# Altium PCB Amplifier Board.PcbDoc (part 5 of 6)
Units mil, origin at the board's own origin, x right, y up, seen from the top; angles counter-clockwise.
Board outline 6000 x 2640 mil, 6 copper layers (Top Layer, GND, VCC, BASES, GND (Plane3), Bottom Layer), stack 63.9 mil thick; 884 components, 484 nets, 2029 pads, 464 vias.
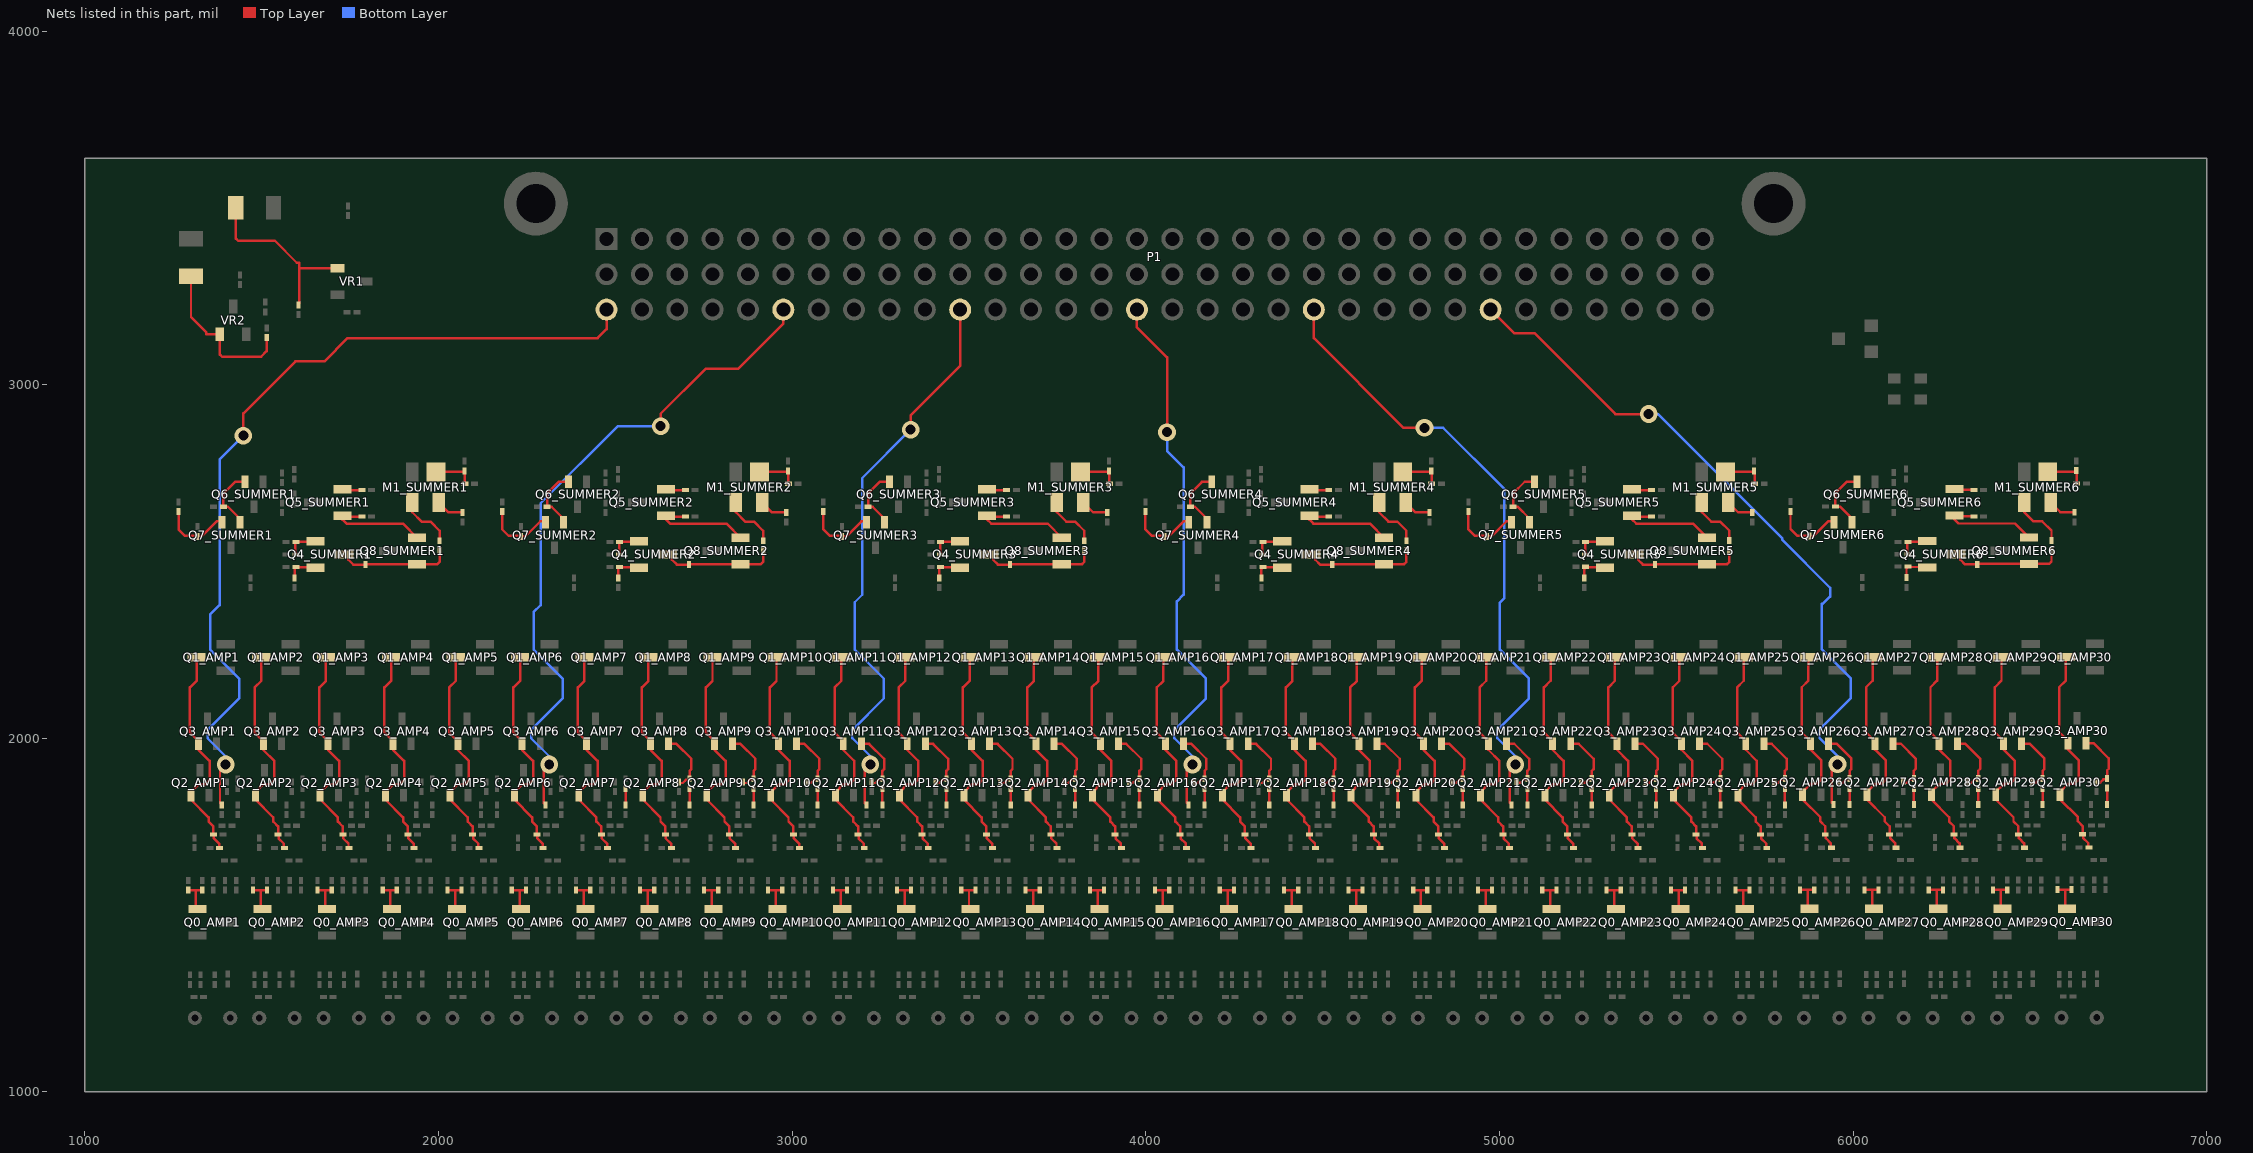
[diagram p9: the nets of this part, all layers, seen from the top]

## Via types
v1: diameter 50, hole 28, Top Layer to Bottom Layer, 433 vias
v2: diameter 50, hole 28, Top Layer to Bottom Layer, tented top, 31 vias

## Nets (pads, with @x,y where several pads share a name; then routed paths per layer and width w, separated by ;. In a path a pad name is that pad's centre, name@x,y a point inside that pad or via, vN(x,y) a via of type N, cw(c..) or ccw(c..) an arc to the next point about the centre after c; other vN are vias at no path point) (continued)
NetC6_AMP7_2: C6_AMP7.2 R7_AMP7.1 | length 42.4
  Top Layer w7: R7_AMP7.1@2529,1812.78 C6_AMP7.2@2529,1855.22
NetC6_AMP8_1: C6_AMP8.1 Q3_AMP8.2 R8_AMP8.1 | length 177.2
  Top Layer w7: Q3_AMP8.2@2650.59,1984.57 2672.68,1984.57 2715,1942.24 2715,1912.94 2710,1907.94 C6_AMP8.1@2710,1885.78 2710,1882.78 2699.59,1882.78 2690.59,1873.78 R8_AMP8.1@2680,1873.78
NetC6_AMP8_2: C6_AMP8.2 R7_AMP8.1 | length 42.4
  Top Layer w7: R7_AMP8.1@2710,1812.78 C6_AMP8.2@2710,1855.22
NetC6_AMP9_1: C6_AMP9.1 Q3_AMP9.2 R8_AMP9.1 | length 177.2
  Top Layer w7: Q3_AMP9.2@2831.59,1984.57 2853.68,1984.57 2896,1942.24 2896,1912.94 2891,1907.94 C6_AMP9.1@2891,1885.78 2891,1882.78 2880.59,1882.78 2871.59,1873.78 R8_AMP9.1@2861,1873.78
NetC6_AMP9_2: C6_AMP9.2 R7_AMP9.1 | length 42.4
  Top Layer w7: R7_AMP9.1@2891,1812.78 C6_AMP9.2@2891,1855.22
NetC6_AMP10_1: C6_AMP10.1 Q3_AMP10.2 R8_AMP10.1 | length 177.2
  Top Layer w7: Q3_AMP10.2@3012.59,1984.57 3034.68,1984.57 3077,1942.24 3077,1912.94 3072,1907.94 C6_AMP10.1@3072,1885.78 3072,1882.78 3061.59,1882.78 3052.59,1873.78 R8_AMP10.1@3042,1873.78
NetC6_AMP10_2: C6_AMP10.2 R7_AMP10.1 | length 42.4
  Top Layer w7: R7_AMP10.1@3072,1812.78 C6_AMP10.2@3072,1855.22
NetC6_AMP11_1: C6_AMP11.1 Q3_AMP11.2 R8_AMP11.1 | length 177.2
  Top Layer w7: Q3_AMP11.2@3195.59,1984.57 3217.68,1984.57 3260,1942.24 3260,1912.94 3255,1907.94 C6_AMP11.1@3255,1885.78 3255,1882.78 3244.59,1882.78 3235.59,1873.78 R8_AMP11.1@3225,1873.78
NetC6_AMP11_2: C6_AMP11.2 R7_AMP11.1 | length 42.4
  Top Layer w7: R7_AMP11.1@3255,1812.78 C6_AMP11.2@3255,1855.22
NetC6_AMP12_1: C6_AMP12.1 Q3_AMP12.2 R8_AMP12.1 | length 177.2
  Top Layer w7: Q3_AMP12.2@3376.59,1984.57 3398.68,1984.57 3441,1942.24 3441,1912.94 3436,1907.94 C6_AMP12.1@3436,1885.78 3436,1882.78 3425.59,1882.78 3416.59,1873.78 R8_AMP12.1@3406,1873.78
NetC6_AMP12_2: C6_AMP12.2 R7_AMP12.1 | length 42.4
  Top Layer w7: R7_AMP12.1@3436,1812.78 C6_AMP12.2@3436,1855.22
NetC6_AMP13_1: C6_AMP13.1 Q3_AMP13.2 R8_AMP13.1 | length 177.2
  Top Layer w7: Q3_AMP13.2@3558.59,1984.57 3580.68,1984.57 3623,1942.24 3623,1912.94 3618,1907.94 C6_AMP13.1@3618,1885.78 3618,1882.78 3607.59,1882.78 3598.59,1873.78 R8_AMP13.1@3588,1873.78
NetC6_AMP13_2: C6_AMP13.2 R7_AMP13.1 | length 42.4
  Top Layer w7: R7_AMP13.1@3618,1812.78 C6_AMP13.2@3618,1855.22
NetC6_AMP14_1: C6_AMP14.1 Q3_AMP14.2 R8_AMP14.1 | length 177.2
  Top Layer w7: Q3_AMP14.2@3740.59,1984.57 3762.68,1984.57 3805,1942.24 3805,1912.94 3800,1907.94 C6_AMP14.1@3800,1885.78 3800,1882.78 3789.59,1882.78 3780.59,1873.78 R8_AMP14.1@3770,1873.78
NetC6_AMP14_2: C6_AMP14.2 R7_AMP14.1 | length 42.4
  Top Layer w7: R7_AMP14.1@3800,1812.78 C6_AMP14.2@3800,1855.22
NetC6_AMP15_1: C6_AMP15.1 Q3_AMP15.2 R8_AMP15.1 | length 177.2
  Top Layer w7: Q3_AMP15.2@3922.59,1984.57 3944.68,1984.57 3987,1942.24 3987,1912.94 3982,1907.94 C6_AMP15.1@3982,1885.78 3982,1882.78 3971.59,1882.78 3962.59,1873.78 R8_AMP15.1@3952,1873.78
NetC6_AMP15_2: C6_AMP15.2 R7_AMP15.1 | length 42.4
  Top Layer w7: R7_AMP15.1@3982,1812.78 C6_AMP15.2@3982,1855.22
NetC6_AMP16_1: C6_AMP16.1 Q3_AMP16.2 R8_AMP16.1 | length 177.2
  Top Layer w7: Q3_AMP16.2@4106.59,1984.57 4128.68,1984.57 4171,1942.24 4171,1912.94 4166,1907.94 C6_AMP16.1@4166,1885.78 4166,1882.78 4155.59,1882.78 4146.59,1873.78 R8_AMP16.1@4136,1873.78
NetC6_AMP16_2: C6_AMP16.2 R7_AMP16.1 | length 42.4
  Top Layer w7: R7_AMP16.1@4166,1812.78 C6_AMP16.2@4166,1855.22
NetC6_AMP17_1: C6_AMP17.1 Q3_AMP17.2 R8_AMP17.1 | length 177.2
  Top Layer w7: Q3_AMP17.2@4289.59,1984.57 4311.68,1984.57 4354,1942.24 4354,1912.94 4349,1907.94 C6_AMP17.1@4349,1885.78 4349,1882.78 4338.59,1882.78 4329.59,1873.78 R8_AMP17.1@4319,1873.78
NetC6_AMP17_2: C6_AMP17.2 R7_AMP17.1 | length 42.4
  Top Layer w7: R7_AMP17.1@4349,1812.78 C6_AMP17.2@4349,1855.22
NetC6_AMP18_1: C6_AMP18.1 Q3_AMP18.2 R8_AMP18.1 | length 177.2
  Top Layer w7: Q3_AMP18.2@4471.59,1984.57 4493.68,1984.57 4536,1942.24 4536,1912.94 4531,1907.94 C6_AMP18.1@4531,1885.78 4531,1882.78 4520.59,1882.78 4511.59,1873.78 R8_AMP18.1@4501,1873.78
NetC6_AMP18_2: C6_AMP18.2 R7_AMP18.1 | length 42.4
  Top Layer w7: R7_AMP18.1@4531,1812.78 C6_AMP18.2@4531,1855.22
NetC6_AMP19_1: C6_AMP19.1 Q3_AMP19.2 R8_AMP19.1 | length 177.2
  Top Layer w7: Q3_AMP19.2@4653.59,1984.57 4675.68,1984.57 4718,1942.24 4718,1912.94 4713,1907.94 C6_AMP19.1@4713,1885.78 4713,1882.78 4702.59,1882.78 4693.59,1873.78 R8_AMP19.1@4683,1873.78
NetC6_AMP19_2: C6_AMP19.2 R7_AMP19.1 | length 42.4
  Top Layer w7: R7_AMP19.1@4713,1812.78 C6_AMP19.2@4713,1855.22
NetC6_AMP20_1: C6_AMP20.1 Q3_AMP20.2 R8_AMP20.1 | length 177.2
  Top Layer w7: Q3_AMP20.2@4836.59,1984.57 4858.68,1984.57 4901,1942.24 4901,1912.94 4896,1907.94 C6_AMP20.1@4896,1885.78 4896,1882.78 4885.59,1882.78 4876.59,1873.78 R8_AMP20.1@4866,1873.78
NetC6_AMP20_2: C6_AMP20.2 R7_AMP20.1 | length 42.4
  Top Layer w7: R7_AMP20.1@4896,1812.78 C6_AMP20.2@4896,1855.22
NetC6_AMP21_1: C6_AMP21.1 Q3_AMP21.2 R8_AMP21.1 | length 177.2
  Top Layer w7: Q3_AMP21.2@5019.59,1984.67 5041.68,1984.67 5084,1942.35 5084,1913.04 5079,1908.04 C6_AMP21.1@5079,1885.88 5079,1882.88 5068.59,1882.88 5059.59,1873.88 R8_AMP21.1@5049,1873.88
NetC6_AMP21_2: C6_AMP21.2 R7_AMP21.1 | length 42.4
  Top Layer w7: R7_AMP21.1@5079,1812.88 C6_AMP21.2@5079,1855.32
NetC6_AMP22_1: C6_AMP22.1 Q3_AMP22.2 R8_AMP22.1 | length 177.2
  Top Layer w7: Q3_AMP22.2@5201.59,1984.67 5223.68,1984.67 5266,1942.35 5266,1913.04 5261,1908.04 C6_AMP22.1@5261,1885.88 5261,1882.88 5250.59,1882.88 5241.59,1873.88 R8_AMP22.1@5231,1873.88
NetC6_AMP22_2: C6_AMP22.2 R7_AMP22.1 | length 42.4
  Top Layer w7: R7_AMP22.1@5261,1812.88 C6_AMP22.2@5261,1855.32
NetC6_AMP23_1: C6_AMP23.1 Q3_AMP23.2 R8_AMP23.1 | length 177.2
  Top Layer w7: Q3_AMP23.2@5383.59,1984.67 5405.68,1984.67 5448,1942.35 5448,1913.04 5443,1908.04 C6_AMP23.1@5443,1885.88 5443,1882.88 5432.59,1882.88 5423.59,1873.88 R8_AMP23.1@5413,1873.88
NetC6_AMP23_2: C6_AMP23.2 R7_AMP23.1 | length 42.4
  Top Layer w7: R7_AMP23.1@5443,1812.88 C6_AMP23.2@5443,1855.32
NetC6_AMP24_1: C6_AMP24.1 Q3_AMP24.2 R8_AMP24.1 | length 177.2
  Top Layer w7: Q3_AMP24.2@5565.59,1984.67 5587.68,1984.67 5630,1942.35 5630,1913.04 5625,1908.04 C6_AMP24.1@5625,1885.88 5625,1882.88 5614.59,1882.88 5605.59,1873.88 R8_AMP24.1@5595,1873.88
NetC6_AMP24_2: C6_AMP24.2 R7_AMP24.1 | length 42.4
  Top Layer w7: R7_AMP24.1@5625,1812.88 C6_AMP24.2@5625,1855.32
NetC6_AMP25_1: C6_AMP25.1 Q3_AMP25.2 R8_AMP25.1 | length 177.2
  Top Layer w7: Q3_AMP25.2@5747.59,1984.67 5769.68,1984.67 5812,1942.35 5812,1913.04 5807,1908.04 C6_AMP25.1@5807,1885.88 5807,1882.88 5796.59,1882.88 5787.59,1873.88 R8_AMP25.1@5777,1873.88
NetC6_AMP25_2: C6_AMP25.2 R7_AMP25.1 | length 42.4
  Top Layer w7: R7_AMP25.1@5807,1812.88 C6_AMP25.2@5807,1855.32
NetC6_AMP26_1: C6_AMP26.1 Q3_AMP26.2 R8_AMP26.1 | length 177.2
  Top Layer w7: Q3_AMP26.2@5930.59,1985.14 5952.68,1985.14 5995,1942.81 5995,1913.51 5990,1908.51 C6_AMP26.1@5990,1886.35 5990,1883.35 5979.59,1883.35 5970.59,1874.35 R8_AMP26.1@5960,1874.35
NetC6_AMP26_2: C6_AMP26.2 R7_AMP26.1 | length 42.4
  Top Layer w7: R7_AMP26.1@5990,1813.35 C6_AMP26.2@5990,1855.79
NetC6_AMP27_1: C6_AMP27.1 Q3_AMP27.2 R8_AMP27.1 | length 177.2
  Top Layer w7: Q3_AMP27.2@6112.59,1985.14 6134.68,1985.14 6177,1942.81 6177,1913.51 6172,1908.51 C6_AMP27.1@6172,1886.35 6172,1883.35 6161.59,1883.35 6152.59,1874.35 R8_AMP27.1@6142,1874.35
NetC6_AMP27_2: C6_AMP27.2 R7_AMP27.1 | length 42.4
  Top Layer w7: R7_AMP27.1@6172,1813.35 C6_AMP27.2@6172,1855.79
NetC6_AMP28_1: C6_AMP28.1 Q3_AMP28.2 R8_AMP28.1 | length 177.2
  Top Layer w7: Q3_AMP28.2@6294.59,1985.14 6316.68,1985.14 6359,1942.81 6359,1913.51 6354,1908.51 C6_AMP28.1@6354,1886.35 6354,1883.35 6343.59,1883.35 6334.59,1874.35 R8_AMP28.1@6324,1874.35
NetC6_AMP28_2: C6_AMP28.2 R7_AMP28.1 | length 42.4
  Top Layer w7: R7_AMP28.1@6354,1813.35 C6_AMP28.2@6354,1855.79
NetC6_AMP29_1: C6_AMP29.1 Q3_AMP29.2 R8_AMP29.1 | length 177.2
  Top Layer w7: Q3_AMP29.2@6476.59,1985.14 6498.68,1985.14 6541,1942.81 6541,1913.51 6536,1908.51 C6_AMP29.1@6536,1886.35 6536,1883.35 6525.59,1883.35 6516.59,1874.35 R8_AMP29.1@6506,1874.35
NetC6_AMP29_2: C6_AMP29.2 R7_AMP29.1 | length 42.4
  Top Layer w7: R7_AMP29.1@6536,1813.35 C6_AMP29.2@6536,1855.79
NetC6_AMP30_1: C6_AMP30.1 Q3_AMP30.2 R8_AMP30.1 | length 177.2
  Top Layer w7: Q3_AMP30.2@6658.59,1985.57 6680.68,1985.57 6723,1943.24 6723,1913.94 6718,1908.94 C6_AMP30.1@6718,1886.78 6718,1883.78 6707.59,1883.78 6698.59,1874.78 R8_AMP30.1@6688,1874.78
NetC6_AMP30_2: C6_AMP30.2 R7_AMP30.1 | length 42.4
  Top Layer w7: R7_AMP30.1@6718,1813.78 C6_AMP30.2@6718,1856.22
NetC7_SUMMER1_2: C7_SUMMER1.2 Q4_SUMMER1.2 R12_SUMMER1.2 | length 76.4
  Top Layer w7: C7_SUMMER1.2@1593,2453.78 1593,2479.22 1597.78,2484 Q4_SUMMER1.2@1642,2484
NetC7_SUMMER2_2: C7_SUMMER2.2 Q4_SUMMER2.2 R12_SUMMER2.2 | length 76.4
  Top Layer w7: C7_SUMMER2.2@2508,2453.78 2508,2479.22 2512.78,2484 Q4_SUMMER2.2@2557,2484
NetC7_SUMMER3_2: C7_SUMMER3.2 Q4_SUMMER3.2 R12_SUMMER3.2 | length 76.4
  Top Layer w7: C7_SUMMER3.2@3416,2453.78 3416,2479.22 3420.78,2484 Q4_SUMMER3.2@3465,2484
NetC7_SUMMER4_2: C7_SUMMER4.2 Q4_SUMMER4.2 R12_SUMMER4.2 | length 76.4
  Top Layer w7: C7_SUMMER4.2@4327,2453.78 4327,2479.22 4331.78,2484 Q4_SUMMER4.2@4376,2484
NetC7_SUMMER5_2: C7_SUMMER5.2 Q4_SUMMER5.2 R12_SUMMER5.2 | length 76.4
  Top Layer w7: C7_SUMMER5.2@5240,2453.88 5240,2479.32 5244.78,2484.1 Q4_SUMMER5.2@5289,2484.1
NetC7_SUMMER6_2: C7_SUMMER6.2 Q4_SUMMER6.2 R12_SUMMER6.2 | length 76.4
  Top Layer w7: C7_SUMMER6.2@6151,2454.35 6151,2479.79 6155.78,2484.57 Q4_SUMMER6.2@6200,2484.57
NetC8_SUMMER1_1: C8_SUMMER1.1 Q4_SUMMER1.3 Q8_SUMMER1.1 R11_SUMMER1.1 | length 315.6
  Top Layer w7: Q4_SUMMER1.3@1745,2522 1745,2520 1745,2505 1758.78,2491.22 R11_SUMMER1.1@1793,2491.22 ; R11_SUMMER1.1@1793,2492.6 Q8_SUMMER1.1@1939.34,2492.6 1996.6,2492.6 2003,2499 C8_SUMMER1.1@2003,2531.22
NetC8_SUMMER1_2: C8_SUMMER1.2 M1_SUMMER1.3 | length 154.6
  Top Layer w7: M1_SUMMER1.3@1925.6,2666.69 1925.6,2639.4 1952,2613 1977,2613 2003,2587 C8_SUMMER1.2@2003,2558.78
NetC8_SUMMER2_1: C8_SUMMER2.1 Q4_SUMMER2.3 Q8_SUMMER2.1 R11_SUMMER2.1 | length 315.6
  Top Layer w7: Q4_SUMMER2.3@2660,2522 2660,2520 2660,2505 2673.78,2491.22 R11_SUMMER2.1@2708,2491.22 ; R11_SUMMER2.1@2708,2492.6 Q8_SUMMER2.1@2854.34,2492.6 2911.6,2492.6 2918,2499 C8_SUMMER2.1@2918,2531.22
NetC8_SUMMER2_2: C8_SUMMER2.2 M1_SUMMER2.3 | length 154.6
  Top Layer w7: M1_SUMMER2.3@2840.6,2666.69 2840.6,2639.4 2867,2613 2892,2613 2918,2587 C8_SUMMER2.2@2918,2558.78
NetC8_SUMMER3_1: C8_SUMMER3.1 Q4_SUMMER3.3 Q8_SUMMER3.1 R11_SUMMER3.1 | length 315.6
  Top Layer w7: Q4_SUMMER3.3@3568,2522 3568,2520 3568,2505 3581.78,2491.22 R11_SUMMER3.1@3616,2491.22 ; R11_SUMMER3.1@3616,2492.6 Q8_SUMMER3.1@3762.34,2492.6 3819.6,2492.6 3826,2499 C8_SUMMER3.1@3826,2531.22
NetC8_SUMMER3_2: C8_SUMMER3.2 M1_SUMMER3.3 | length 154.6
  Top Layer w7: M1_SUMMER3.3@3748.6,2666.69 3748.6,2639.4 3775,2613 3800,2613 3826,2587 C8_SUMMER3.2@3826,2558.78
NetC8_SUMMER4_1: C8_SUMMER4.1 Q4_SUMMER4.3 Q8_SUMMER4.1 R11_SUMMER4.1 | length 315.6
  Top Layer w7: Q4_SUMMER4.3@4479,2522 4479,2520 4479,2505 4492.78,2491.22 R11_SUMMER4.1@4527,2491.22 ; R11_SUMMER4.1@4527,2492.6 Q8_SUMMER4.1@4673.34,2492.6 4730.6,2492.6 4737,2499 C8_SUMMER4.1@4737,2531.22
NetC8_SUMMER4_2: C8_SUMMER4.2 M1_SUMMER4.3 | length 154.6
  Top Layer w7: M1_SUMMER4.3@4659.6,2666.69 4659.6,2639.4 4686,2613 4711,2613 4737,2587 C8_SUMMER4.2@4737,2558.78
NetC8_SUMMER5_1: C8_SUMMER5.1 Q4_SUMMER5.3 Q8_SUMMER5.1 R11_SUMMER5.1 | length 315.6
  Top Layer w7: Q4_SUMMER5.3@5392,2522.1 5392,2520.1 5392,2505.1 5405.78,2491.32 R11_SUMMER5.1@5440,2491.32 ; R11_SUMMER5.1@5440,2492.7 Q8_SUMMER5.1@5586.34,2492.7 5643.6,2492.7 5650,2499.1 C8_SUMMER5.1@5650,2531.32
NetC8_SUMMER5_2: C8_SUMMER5.2 M1_SUMMER5.3 | length 154.6
  Top Layer w7: M1_SUMMER5.3@5572.6,2666.8 5572.6,2639.5 5599,2613.1 5624,2613.1 5650,2587.1 C8_SUMMER5.2@5650,2558.88
NetC8_SUMMER6_1: C8_SUMMER6.1 Q4_SUMMER6.3 Q8_SUMMER6.1 R11_SUMMER6.1 | length 315.6
  Top Layer w7: Q4_SUMMER6.3@6303,2522.57 6303,2520.57 6303,2505.57 6316.78,2491.79 R11_SUMMER6.1@6351,2491.79 ; R11_SUMMER6.1@6351,2493.17 Q8_SUMMER6.1@6497.34,2493.17 6554.6,2493.17 6561,2499.57 C8_SUMMER6.1@6561,2531.79
NetC8_SUMMER6_2: C8_SUMMER6.2 M1_SUMMER6.3 | length 154.6
  Top Layer w7: M1_SUMMER6.3@6483.6,2667.26 6483.6,2639.97 6510,2613.57 6535,2613.57 6561,2587.57 C8_SUMMER6.2@6561,2559.35
NetC9_SUMMER1_1: C9_SUMMER1.1 Q7_SUMMER1.2 R16_SUMMER1.1 | length 195.9
  Top Layer w7: C9_SUMMER1.1@1265,2642.6 C9_SUMMER1.1@1265,2641.22 1265,2591 1283.4,2572.6 R16_SUMMER1.1@1318,2572.6 ; R16_SUMMER1.1@1318,2571.22 1330.06,2571.22 1372.57,2613.72 Q7_SUMMER1.2@1384.12,2613.72
NetC9_SUMMER2_1: C9_SUMMER2.1 Q7_SUMMER2.2 R16_SUMMER2.1 | length 195.9
  Top Layer w7: C9_SUMMER2.1@2180,2642.6 C9_SUMMER2.1@2180,2641.22 2180,2591 2198.4,2572.6 R16_SUMMER2.1@2233,2572.6 ; R16_SUMMER2.1@2233,2571.22 2245.06,2571.22 2287.57,2613.72 Q7_SUMMER2.2@2299.12,2613.72
NetC9_SUMMER3_1: C9_SUMMER3.1 Q7_SUMMER3.2 R16_SUMMER3.1 | length 195.9
  Top Layer w7: C9_SUMMER3.1@3088,2642.6 C9_SUMMER3.1@3088,2641.22 3088,2591 3106.4,2572.6 R16_SUMMER3.1@3141,2572.6 ; R16_SUMMER3.1@3141,2571.22 3153.06,2571.22 3195.57,2613.72 Q7_SUMMER3.2@3207.12,2613.72
NetC9_SUMMER4_1: C9_SUMMER4.1 Q7_SUMMER4.2 R16_SUMMER4.1 | length 195.9
  Top Layer w7: C9_SUMMER4.1@3999,2642.6 C9_SUMMER4.1@3999,2641.22 3999,2591 4017.4,2572.6 R16_SUMMER4.1@4052,2572.6 ; R16_SUMMER4.1@4052,2571.22 4064.06,2571.22 4106.57,2613.72 Q7_SUMMER4.2@4118.12,2613.72
NetC9_SUMMER5_1: C9_SUMMER5.1 Q7_SUMMER5.2 R16_SUMMER5.1 | length 195.9
  Top Layer w7: C9_SUMMER5.1@4912,2642.7 C9_SUMMER5.1@4912,2641.32 4912,2591.1 4930.4,2572.7 R16_SUMMER5.1@4965,2572.7 ; R16_SUMMER5.1@4965,2571.32 4977.06,2571.32 5019.57,2613.83 Q7_SUMMER5.2@5031.12,2613.83
NetC9_SUMMER6_1: C9_SUMMER6.1 Q7_SUMMER6.2 R16_SUMMER6.1 | length 195.9
  Top Layer w7: C9_SUMMER6.1@5823,2643.17 C9_SUMMER6.1@5823,2641.79 5823,2591.57 5841.4,2573.17 R16_SUMMER6.1@5876,2573.17 ; R16_SUMMER6.1@5876,2571.79 5888.06,2571.79 5930.57,2614.29 Q7_SUMMER6.2@5942.12,2614.29
NetCBi_AMP1_1: CBi_AMP1.1 Q0_AMP1.1 RBi_AMP1.2 | length 93.6
  Top Layer w7: CBi_AMP1.1@1292,1571 1314,1571 ; Q0_AMP1.1@1314,1517.4 1314,1571 ; RBi_AMP1.2@1332,1571 1314,1571
NetCBi_AMP2_1: CBi_AMP2.1 Q0_AMP2.1 RBi_AMP2.2 | length 93.6
  Top Layer w7: CBi_AMP2.1@1475,1571 1497,1571 ; Q0_AMP2.1@1497,1517.4 1497,1571 ; RBi_AMP2.2@1515,1571 1497,1571
NetCBi_AMP3_1: CBi_AMP3.1 Q0_AMP3.1 RBi_AMP3.2 | length 93.6
  Top Layer w7: CBi_AMP3.1@1658,1571 1680,1571 ; Q0_AMP3.1@1680,1517.4 1680,1571 ; RBi_AMP3.2@1698,1571 1680,1571
NetCBi_AMP4_1: CBi_AMP4.1 Q0_AMP4.1 RBi_AMP4.2 | length 93.6
  Top Layer w7: CBi_AMP4.1@1842,1571 1864,1571 ; Q0_AMP4.1@1864,1517.4 1864,1571 ; RBi_AMP4.2@1882,1571 1864,1571
NetCBi_AMP5_1: CBi_AMP5.1 Q0_AMP5.1 RBi_AMP5.2 | length 93.6
  Top Layer w7: CBi_AMP5.1@2025,1571 2047,1571 ; Q0_AMP5.1@2047,1517.4 2047,1571 ; RBi_AMP5.2@2065,1571 2047,1571
NetCBi_AMP6_1: CBi_AMP6.1 Q0_AMP6.1 RBi_AMP6.2 | length 93.6
  Top Layer w7: CBi_AMP6.1@2207,1571 2229,1571 ; Q0_AMP6.1@2229,1517.4 2229,1571 ; RBi_AMP6.2@2247,1571 2229,1571
NetCBi_AMP7_1: CBi_AMP7.1 Q0_AMP7.1 RBi_AMP7.2 | length 93.6
  Top Layer w7: CBi_AMP7.1@2389,1571 2411,1571 ; Q0_AMP7.1@2411,1517.4 2411,1571 ; RBi_AMP7.2@2429,1571 2411,1571
NetCBi_AMP8_1: CBi_AMP8.1 Q0_AMP8.1 RBi_AMP8.2 | length 93.6
  Top Layer w7: CBi_AMP8.1@2570,1571 2592,1571 ; Q0_AMP8.1@2592,1517.4 2592,1571 ; RBi_AMP8.2@2610,1571 2592,1571
NetCBi_AMP9_1: CBi_AMP9.1 Q0_AMP9.1 RBi_AMP9.2 | length 93.6
  Top Layer w7: CBi_AMP9.1@2751,1571 2773,1571 ; Q0_AMP9.1@2773,1517.4 2773,1571 ; RBi_AMP9.2@2791,1571 2773,1571
NetCBi_AMP10_1: CBi_AMP10.1 Q0_AMP10.1 RBi_AMP10.2 | length 93.6
  Top Layer w7: CBi_AMP10.1@2932,1571 2954,1571 ; Q0_AMP10.1@2954,1517.4 2954,1571 ; RBi_AMP10.2@2972,1571 2954,1571
NetCBi_AMP11_1: CBi_AMP11.1 Q0_AMP11.1 RBi_AMP11.2 | length 93.6
  Top Layer w7: CBi_AMP11.1@3115,1571 3137,1571 ; Q0_AMP11.1@3137,1517.4 3137,1571 ; RBi_AMP11.2@3155,1571 3137,1571
NetCBi_AMP12_1: CBi_AMP12.1 Q0_AMP12.1 RBi_AMP12.2 | length 93.6
  Top Layer w7: CBi_AMP12.1@3296,1571 3318,1571 ; Q0_AMP12.1@3318,1517.4 3318,1571 ; RBi_AMP12.2@3336,1571 3318,1571
NetCBi_AMP13_1: CBi_AMP13.1 Q0_AMP13.1 RBi_AMP13.2 | length 93.6
  Top Layer w7: CBi_AMP13.1@3478,1571 3500,1571 ; Q0_AMP13.1@3500,1517.4 3500,1571 ; RBi_AMP13.2@3518,1571 3500,1571
NetCBi_AMP14_1: CBi_AMP14.1 Q0_AMP14.1 RBi_AMP14.2 | length 93.6
  Top Layer w7: CBi_AMP14.1@3660,1571 3682,1571 ; Q0_AMP14.1@3682,1517.4 3682,1571 ; RBi_AMP14.2@3700,1571 3682,1571
NetCBi_AMP15_1: CBi_AMP15.1 Q0_AMP15.1 RBi_AMP15.2 | length 93.6
  Top Layer w7: CBi_AMP15.1@3842,1571 3864,1571 ; Q0_AMP15.1@3864,1517.4 3864,1571 ; RBi_AMP15.2@3882,1571 3864,1571
NetCBi_AMP16_1: CBi_AMP16.1 Q0_AMP16.1 RBi_AMP16.2 | length 93.6
  Top Layer w7: CBi_AMP16.1@4026,1571 4048,1571 ; Q0_AMP16.1@4048,1517.4 4048,1571 ; RBi_AMP16.2@4066,1571 4048,1571
NetCBi_AMP17_1: CBi_AMP17.1 Q0_AMP17.1 RBi_AMP17.2 | length 93.6
  Top Layer w7: CBi_AMP17.1@4209,1571 4231,1571 ; Q0_AMP17.1@4231,1517.4 4231,1571 ; RBi_AMP17.2@4249,1571 4231,1571
NetCBi_AMP18_1: CBi_AMP18.1 Q0_AMP18.1 RBi_AMP18.2 | length 93.6
  Top Layer w7: CBi_AMP18.1@4391,1571 4413,1571 ; Q0_AMP18.1@4413,1517.4 4413,1571 ; RBi_AMP18.2@4431,1571 4413,1571
NetCBi_AMP19_1: CBi_AMP19.1 Q0_AMP19.1 RBi_AMP19.2 | length 93.6
  Top Layer w7: CBi_AMP19.1@4573,1571 4595,1571 ; Q0_AMP19.1@4595,1517.4 4595,1571 ; RBi_AMP19.2@4613,1571 4595,1571
NetCBi_AMP20_1: CBi_AMP20.1 Q0_AMP20.1 RBi_AMP20.2 | length 93.6
  Top Layer w7: CBi_AMP20.1@4756,1571 4778,1571 ; Q0_AMP20.1@4778,1517.4 4778,1571 ; RBi_AMP20.2@4796,1571 4778,1571
NetCBi_AMP21_1: CBi_AMP21.1 Q0_AMP21.1 RBi_AMP21.2 | length 93.6
  Top Layer w7: CBi_AMP21.1@4939,1571.1 4961,1571.1 ; Q0_AMP21.1@4961,1517.5 4961,1571.1 ; RBi_AMP21.2@4979,1571.1 4961,1571.1
NetCBi_AMP22_1: CBi_AMP22.1 Q0_AMP22.1 RBi_AMP22.2 | length 93.6
  Top Layer w7: CBi_AMP22.1@5121,1571.1 5143,1571.1 ; Q0_AMP22.1@5143,1517.5 5143,1571.1 ; RBi_AMP22.2@5161,1571.1 5143,1571.1
NetCBi_AMP23_1: CBi_AMP23.1 Q0_AMP23.1 RBi_AMP23.2 | length 93.6
  Top Layer w7: CBi_AMP23.1@5303,1571.1 5325,1571.1 ; Q0_AMP23.1@5325,1517.5 5325,1571.1 ; RBi_AMP23.2@5343,1571.1 5325,1571.1
NetCBi_AMP24_1: CBi_AMP24.1 Q0_AMP24.1 RBi_AMP24.2 | length 93.6
  Top Layer w7: CBi_AMP24.1@5485,1571.1 5507,1571.1 ; Q0_AMP24.1@5507,1517.5 5507,1571.1 ; RBi_AMP24.2@5525,1571.1 5507,1571.1
NetCBi_AMP25_1: CBi_AMP25.1 Q0_AMP25.1 RBi_AMP25.2 | length 93.6
  Top Layer w7: CBi_AMP25.1@5667,1571.1 5689,1571.1 ; Q0_AMP25.1@5689,1517.5 5689,1571.1 ; RBi_AMP25.2@5707,1571.1 5689,1571.1
NetCBi_AMP26_1: CBi_AMP26.1 Q0_AMP26.1 RBi_AMP26.2 | length 93.6
  Top Layer w7: CBi_AMP26.1@5850,1571.57 5872,1571.57 ; Q0_AMP26.1@5872,1517.97 5872,1571.57 ; RBi_AMP26.2@5890,1571.57 5872,1571.57
NetCBi_AMP27_1: CBi_AMP27.1 Q0_AMP27.1 RBi_AMP27.2 | length 93.6
  Top Layer w7: CBi_AMP27.1@6032,1571.57 6054,1571.57 ; Q0_AMP27.1@6054,1517.97 6054,1571.57 ; RBi_AMP27.2@6072,1571.57 6054,1571.57
NetCBi_AMP28_1: CBi_AMP28.1 Q0_AMP28.1 RBi_AMP28.2 | length 93.6
  Top Layer w7: CBi_AMP28.1@6214,1571.57 6236,1571.57 ; Q0_AMP28.1@6236,1517.97 6236,1571.57 ; RBi_AMP28.2@6254,1571.57 6236,1571.57
NetCBi_AMP29_1: CBi_AMP29.1 Q0_AMP29.1 RBi_AMP29.2 | length 93.6
  Top Layer w7: CBi_AMP29.1@6396,1571.57 6418,1571.57 ; Q0_AMP29.1@6418,1517.97 6418,1571.57 ; RBi_AMP29.2@6436,1571.57 6418,1571.57
NetCBi_AMP30_1: CBi_AMP30.1 Q0_AMP30.1 RBi_AMP30.2 | length 93.6
  Top Layer w7: CBi_AMP30.1@6578,1572 6600,1572 ; Q0_AMP30.1@6600,1518.4 6600,1572 ; RBi_AMP30.2@6618,1572 6600,1572
NetCBi_SUMMER1_1: CBi_SUMMER1.1 Q4_SUMMER1.1 RBi_SUMMER1.2 | length 79.2
  Top Layer w7: RBi_SUMMER1.2@1595.4,2520 CBi_SUMMER1.1@1595.4,2555 ; CBi_SUMMER1.1@1597.78,2556 Q4_SUMMER1.1@1642,2556
NetCBi_SUMMER2_1: CBi_SUMMER2.1 Q4_SUMMER2.1 RBi_SUMMER2.2 | length 79.2
  Top Layer w7: RBi_SUMMER2.2@2510.4,2520 CBi_SUMMER2.1@2510.4,2555 ; CBi_SUMMER2.1@2512.78,2556 Q4_SUMMER2.1@2557,2556
NetCBi_SUMMER3_1: CBi_SUMMER3.1 Q4_SUMMER3.1 RBi_SUMMER3.2 | length 79.2
  Top Layer w7: RBi_SUMMER3.2@3418.4,2520 CBi_SUMMER3.1@3418.4,2555 ; CBi_SUMMER3.1@3420.78,2556 Q4_SUMMER3.1@3465,2556
NetCBi_SUMMER4_1: CBi_SUMMER4.1 Q4_SUMMER4.1 RBi_SUMMER4.2 | length 79.2
  Top Layer w7: RBi_SUMMER4.2@4329.4,2520 CBi_SUMMER4.1@4329.4,2555 ; CBi_SUMMER4.1@4331.78,2556 Q4_SUMMER4.1@4376,2556
NetCBi_SUMMER5_1: CBi_SUMMER5.1 Q4_SUMMER5.1 RBi_SUMMER5.2 | length 79.2
  Top Layer w7: RBi_SUMMER5.2@5242.4,2520.1 CBi_SUMMER5.1@5242.4,2555.1 ; CBi_SUMMER5.1@5244.78,2556.1 Q4_SUMMER5.1@5289,2556.1
NetCBi_SUMMER6_1: CBi_SUMMER6.1 Q4_SUMMER6.1 RBi_SUMMER6.2 | length 79.2
  Top Layer w7: RBi_SUMMER6.2@6153.4,2520.57 CBi_SUMMER6.1@6153.4,2555.57 ; CBi_SUMMER6.1@6155.78,2556.57 Q4_SUMMER6.1@6200,2556.57
NetCG_SUMMER1_1: CG_SUMMER1.1 M1_SUMMER1.1 RG_SUMMER1.1 | length 112.6
  Top Layer w7: M1_SUMMER1.1@1992.53,2753.31 2070.09,2753.31 2074.22,2749.17 CG_SUMMER1.1@2074.22,2720
NetCG_SUMMER2_1: CG_SUMMER2.1 M1_SUMMER2.1 RG_SUMMER2.1 | length 112.6
  Top Layer w7: M1_SUMMER2.1@2907.53,2753.31 2985.09,2753.31 2989.22,2749.17 CG_SUMMER2.1@2989.22,2720
NetCG_SUMMER3_1: CG_SUMMER3.1 M1_SUMMER3.1 RG_SUMMER3.1 | length 112.6
  Top Layer w7: M1_SUMMER3.1@3815.53,2753.31 3893.09,2753.31 3897.22,2749.17 CG_SUMMER3.1@3897.22,2720
NetCG_SUMMER4_1: CG_SUMMER4.1 M1_SUMMER4.1 RG_SUMMER4.1 | length 112.6
  Top Layer w7: M1_SUMMER4.1@4726.53,2753.31 4804.09,2753.31 4808.22,2749.17 CG_SUMMER4.1@4808.22,2720
NetCG_SUMMER5_1: CG_SUMMER5.1 M1_SUMMER5.1 RG_SUMMER5.1 | length 118.4
  Top Layer w7: M1_SUMMER5.1@5639.53,2753.41 RG_SUMMER5.1@5717.09,2753.41 ; CG_SUMMER5.1@5721.22,2720.1 RG_SUMMER5.1@5721.22,2749.28 ; RG_SUMMER5.1@5717.09,2753.41 RG_SUMMER5.1@5721.22,2749.28 ; RG_SUMMER5.1@5717.09,2753.41 RG_SUMMER5.1@5721.22,2749.28
NetCG_SUMMER6_1: CG_SUMMER6.1 M1_SUMMER6.1 RG_SUMMER6.1 | length 118.4
  Top Layer w7: M1_SUMMER6.1@6550.53,2753.88 RG_SUMMER6.1@6628.09,2753.88 ; CG_SUMMER6.1@6632.22,2720.57 RG_SUMMER6.1@6632.22,2749.74 ; RG_SUMMER6.1@6628.09,2753.88 RG_SUMMER6.1@6632.22,2749.74 ; RG_SUMMER6.1@6628.09,2753.88 RG_SUMMER6.1@6632.22,2749.74
NetM1_SUMMER1_4: M1_SUMMER1.4 R10_SUMMER1.1 | length 79.2
  Top Layer w7: M1_SUMMER1.4@2000.4,2666.69 2028.31,2638.78 R10_SUMMER1.1@2068,2638.78
NetM1_SUMMER2_4: M1_SUMMER2.4 R10_SUMMER2.1 | length 79.2
  Top Layer w7: M1_SUMMER2.4@2915.4,2666.69 2943.31,2638.78 R10_SUMMER2.1@2983,2638.78
NetM1_SUMMER3_4: M1_SUMMER3.4 R10_SUMMER3.1 | length 79.2
  Top Layer w7: M1_SUMMER3.4@3823.4,2666.69 3851.31,2638.78 R10_SUMMER3.1@3891,2638.78
NetM1_SUMMER4_4: M1_SUMMER4.4 R10_SUMMER4.1 | length 79.2
  Top Layer w7: M1_SUMMER4.4@4734.4,2666.69 4762.31,2638.78 R10_SUMMER4.1@4802,2638.78
NetM1_SUMMER5_4: M1_SUMMER5.4 R10_SUMMER5.1 | length 79.2
  Top Layer w7: M1_SUMMER5.4@5647.4,2666.8 5675.31,2638.88 R10_SUMMER5.1@5715,2638.88
NetM1_SUMMER6_4: M1_SUMMER6.4 R10_SUMMER6.1 | length 79.2
  Top Layer w7: M1_SUMMER6.4@6558.4,2667.26 6586.31,2639.35 R10_SUMMER6.1@6626,2639.35
NetQ1_AMP1_3: Q1_AMP1.3 Q2_AMP1.1 Q3_AMP1.1 R2_AMP1.2 R4_AMP1.1 | length 623.9
  Top Layer w7: Q2_AMP1.1@1299,1847.44 1322.34,1870.78 1340.47,1870.78 1352.59,1882.91 1352.59,1936.41 1321.41,1967.59 Q3_AMP1.1@1321.41,1984.57 ; Q2_AMP1.1@1299.41,1839.57 1299.41,1826.59 1349.6,1776.4 1349.6,1764.62 1363.22,1751 R4_AMP1.1@1363.22,1728 R4_AMP1.1@1364.6,1726.62 ; Q1_AMP1.3@1315.66,2229 1315.66,2162.66 1296.88,2143.88 1296.88,2016.56 Q3_AMP1.1@1321,1992.44 ; R4_AMP1.1@1364.6,1728 R4_AMP1.1@1364.6,1726.62 ; R4_AMP1.1@1366.49,1724.73 R4_AMP1.1@1364.6,1726.62 ; R2_AMP1.2@1379.4,1690 1379.4,1702.44 1364.6,1717.24 R4_AMP1.1@1364.6,1726.62
NetQ1_AMP2_3: Q1_AMP2.3 Q2_AMP2.1 Q3_AMP2.1 R2_AMP2.2 R4_AMP2.1 | length 623.9
  Top Layer w7: Q2_AMP2.1@1482,1847.44 1505.34,1870.78 1523.47,1870.78 1535.59,1882.91 1535.59,1936.41 1504.41,1967.59 Q3_AMP2.1@1504.41,1984.57 ; Q2_AMP2.1@1482.41,1839.57 1482.41,1826.59 1532.6,1776.4 1532.6,1764.62 1546.22,1751 R4_AMP2.1@1546.22,1728 R4_AMP2.1@1547.6,1726.62 ; Q1_AMP2.3@1498.66,2229 1498.66,2162.66 1479.88,2143.88 1479.88,2016.56 Q3_AMP2.1@1504,1992.44 ; R4_AMP2.1@1547.6,1728 R4_AMP2.1@1547.6,1726.62 ; R4_AMP2.1@1549.49,1724.73 R4_AMP2.1@1547.6,1726.62 ; R2_AMP2.2@1562.4,1690 1562.4,1702.44 1547.6,1717.24 R4_AMP2.1@1547.6,1726.62
NetQ1_AMP3_3: Q1_AMP3.3 Q2_AMP3.1 Q3_AMP3.1 R2_AMP3.2 R4_AMP3.1 | length 623.9
  Top Layer w7: Q2_AMP3.1@1665,1847.44 1688.34,1870.78 1706.47,1870.78 1718.59,1882.91 1718.59,1936.41 1687.41,1967.59 Q3_AMP3.1@1687.41,1984.57 ; Q2_AMP3.1@1665.41,1839.57 1665.41,1826.59 1715.6,1776.4 1715.6,1764.62 1729.22,1751 R4_AMP3.1@1729.22,1728 R4_AMP3.1@1730.6,1726.62 ; Q1_AMP3.3@1681.66,2229 1681.66,2162.66 1662.88,2143.88 1662.88,2016.56 Q3_AMP3.1@1687,1992.44 ; R4_AMP3.1@1730.6,1728 R4_AMP3.1@1730.6,1726.62 ; R4_AMP3.1@1732.49,1724.73 R4_AMP3.1@1730.6,1726.62 ; R2_AMP3.2@1745.4,1690 1745.4,1702.44 1730.6,1717.24 R4_AMP3.1@1730.6,1726.62
NetQ1_AMP4_3: Q1_AMP4.3 Q2_AMP4.1 Q3_AMP4.1 R2_AMP4.2 R4_AMP4.1 | length 623.9
  Top Layer w7: Q2_AMP4.1@1849,1847.44 1872.34,1870.78 1890.47,1870.78 1902.59,1882.91 1902.59,1936.41 1871.41,1967.59 Q3_AMP4.1@1871.41,1984.57 ; Q2_AMP4.1@1849.41,1839.57 1849.41,1826.59 1899.6,1776.4 1899.6,1764.62 1913.22,1751 R4_AMP4.1@1913.22,1728 R4_AMP4.1@1914.6,1726.62 ; Q1_AMP4.3@1865.66,2229 1865.66,2162.66 1846.88,2143.88 1846.88,2016.56 Q3_AMP4.1@1871,1992.44 ; R4_AMP4.1@1914.6,1728 R4_AMP4.1@1914.6,1726.62 ; R4_AMP4.1@1916.49,1724.73 R4_AMP4.1@1914.6,1726.62 ; R2_AMP4.2@1929.4,1690 1929.4,1702.44 1914.6,1717.24 R4_AMP4.1@1914.6,1726.62
NetQ1_AMP5_3: Q1_AMP5.3 Q2_AMP5.1 Q3_AMP5.1 R2_AMP5.2 R4_AMP5.1 | length 623.9
  Top Layer w7: Q2_AMP5.1@2032,1847.44 2055.34,1870.78 2073.47,1870.78 2085.59,1882.91 2085.59,1936.41 2054.41,1967.59 Q3_AMP5.1@2054.41,1984.57 ; Q2_AMP5.1@2032.41,1839.57 2032.41,1826.59 2082.6,1776.4 2082.6,1764.62 2096.22,1751 R4_AMP5.1@2096.22,1728 R4_AMP5.1@2097.6,1726.62 ; Q1_AMP5.3@2048.66,2229 2048.66,2162.66 2029.88,2143.88 2029.88,2016.56 Q3_AMP5.1@2054,1992.44 ; R4_AMP5.1@2097.6,1728 R4_AMP5.1@2097.6,1726.62 ; R4_AMP5.1@2099.49,1724.73 R4_AMP5.1@2097.6,1726.62 ; R2_AMP5.2@2112.4,1690 2112.4,1702.44 2097.6,1717.24 R4_AMP5.1@2097.6,1726.62
NetQ1_AMP6_3: Q1_AMP6.3 Q2_AMP6.1 Q3_AMP6.1 R2_AMP6.2 R4_AMP6.1 | length 623.9
  Top Layer w7: Q2_AMP6.1@2214,1847.44 2237.34,1870.78 2255.47,1870.78 2267.59,1882.91 2267.59,1936.41 2236.41,1967.59 Q3_AMP6.1@2236.41,1984.57 ; Q2_AMP6.1@2214.41,1839.57 2214.41,1826.59 2264.6,1776.4 2264.6,1764.62 2278.22,1751 R4_AMP6.1@2278.22,1728 R4_AMP6.1@2279.6,1726.62 ; Q1_AMP6.3@2230.66,2229 2230.66,2162.66 2211.88,2143.88 2211.88,2016.56 Q3_AMP6.1@2236,1992.44 ; R4_AMP6.1@2279.6,1728 R4_AMP6.1@2279.6,1726.62 ; R4_AMP6.1@2281.49,1724.73 R4_AMP6.1@2279.6,1726.62 ; R2_AMP6.2@2294.4,1690 2294.4,1702.44 2279.6,1717.24 R4_AMP6.1@2279.6,1726.62
NetQ1_AMP7_3: Q1_AMP7.3 Q2_AMP7.1 Q3_AMP7.1 R2_AMP7.2 R4_AMP7.1 | length 623.9
  Top Layer w7: Q2_AMP7.1@2396,1847.44 2419.34,1870.78 2437.47,1870.78 2449.59,1882.91 2449.59,1936.41 2418.41,1967.59 Q3_AMP7.1@2418.41,1984.57 ; Q2_AMP7.1@2396.41,1839.57 2396.41,1826.59 2446.6,1776.4 2446.6,1764.62 2460.22,1751 R4_AMP7.1@2460.22,1728 R4_AMP7.1@2461.6,1726.62 ; Q1_AMP7.3@2412.66,2229 2412.66,2162.66 2393.88,2143.88 2393.88,2016.56 Q3_AMP7.1@2418,1992.44 ; R4_AMP7.1@2461.6,1728 R4_AMP7.1@2461.6,1726.62 ; R4_AMP7.1@2463.49,1724.73 R4_AMP7.1@2461.6,1726.62 ; R2_AMP7.2@2476.4,1690 2476.4,1702.44 2461.6,1717.24 R4_AMP7.1@2461.6,1726.62
NetQ1_AMP8_3: Q1_AMP8.3 Q2_AMP8.1 Q3_AMP8.1 R2_AMP8.2 R4_AMP8.1 | length 623.9
  Top Layer w7: Q2_AMP8.1@2577,1847.44 2600.34,1870.78 2618.47,1870.78 2630.59,1882.91 2630.59,1936.41 2599.41,1967.59 Q3_AMP8.1@2599.41,1984.57 ; Q2_AMP8.1@2577.41,1839.57 2577.41,1826.59 2627.6,1776.4 2627.6,1764.62 2641.22,1751 R4_AMP8.1@2641.22,1728 R4_AMP8.1@2642.6,1726.62 ; Q1_AMP8.3@2593.66,2229 2593.66,2162.66 2574.88,2143.88 2574.88,2016.56 Q3_AMP8.1@2599,1992.44 ; R4_AMP8.1@2642.6,1728 R4_AMP8.1@2642.6,1726.62 ; R4_AMP8.1@2644.49,1724.73 R4_AMP8.1@2642.6,1726.62 ; R2_AMP8.2@2657.4,1690 2657.4,1702.44 2642.6,1717.24 R4_AMP8.1@2642.6,1726.62
NetQ1_AMP9_3: Q1_AMP9.3 Q2_AMP9.1 Q3_AMP9.1 R2_AMP9.2 R4_AMP9.1 | length 623.9
  Top Layer w7: Q2_AMP9.1@2758,1847.44 2781.34,1870.78 2799.47,1870.78 2811.59,1882.91 2811.59,1936.41 2780.41,1967.59 Q3_AMP9.1@2780.41,1984.57 ; Q2_AMP9.1@2758.41,1839.57 2758.41,1826.59 2808.6,1776.4 2808.6,1764.62 2822.22,1751 R4_AMP9.1@2822.22,1728 R4_AMP9.1@2823.6,1726.62 ; Q1_AMP9.3@2774.66,2229 2774.66,2162.66 2755.88,2143.88 2755.88,2016.56 Q3_AMP9.1@2780,1992.44 ; R4_AMP9.1@2823.6,1728 R4_AMP9.1@2823.6,1726.62 ; R4_AMP9.1@2825.49,1724.73 R4_AMP9.1@2823.6,1726.62 ; R2_AMP9.2@2838.4,1690 2838.4,1702.44 2823.6,1717.24 R4_AMP9.1@2823.6,1726.62
NetQ1_AMP10_3: Q1_AMP10.3 Q2_AMP10.1 Q3_AMP10.1 R2_AMP10.2 R4_AMP10.1 | length 623.9
  Top Layer w7: Q2_AMP10.1@2939,1847.44 2962.34,1870.78 2980.47,1870.78 2992.59,1882.91 2992.59,1936.41 2961.41,1967.59 Q3_AMP10.1@2961.41,1984.57 ; Q2_AMP10.1@2939.41,1839.57 2939.41,1826.59 2989.6,1776.4 2989.6,1764.62 3003.22,1751 R4_AMP10.1@3003.22,1728 R4_AMP10.1@3004.6,1726.62 ; Q1_AMP10.3@2955.66,2229 2955.66,2162.66 2936.88,2143.88 2936.88,2016.56 Q3_AMP10.1@2961,1992.44 ; R4_AMP10.1@3004.6,1728 R4_AMP10.1@3004.6,1726.62 ; R4_AMP10.1@3006.49,1724.73 R4_AMP10.1@3004.6,1726.62 ; R2_AMP10.2@3019.4,1690 3019.4,1702.44 3004.6,1717.24 R4_AMP10.1@3004.6,1726.62
NetQ1_AMP11_3: Q1_AMP11.3 Q2_AMP11.1 Q3_AMP11.1 R2_AMP11.2 R4_AMP11.1 | length 623.9
  Top Layer w7: Q2_AMP11.1@3122,1847.44 3145.34,1870.78 3163.47,1870.78 3175.59,1882.91 3175.59,1936.41 3144.41,1967.59 Q3_AMP11.1@3144.41,1984.57 ; Q2_AMP11.1@3122.41,1839.57 3122.41,1826.59 3172.6,1776.4 3172.6,1764.62 3186.22,1751 R4_AMP11.1@3186.22,1728 R4_AMP11.1@3187.6,1726.62 ; Q1_AMP11.3@3138.66,2229 3138.66,2162.66 3119.88,2143.88 3119.88,2016.56 Q3_AMP11.1@3144,1992.44 ; R4_AMP11.1@3187.6,1728 R4_AMP11.1@3187.6,1726.62 ; R4_AMP11.1@3189.49,1724.73 R4_AMP11.1@3187.6,1726.62 ; R2_AMP11.2@3202.4,1690 3202.4,1702.44 3187.6,1717.24 R4_AMP11.1@3187.6,1726.62
NetQ1_AMP12_3: Q1_AMP12.3 Q2_AMP12.1 Q3_AMP12.1 R2_AMP12.2 R4_AMP12.1 | length 623.9
  Top Layer w7: Q2_AMP12.1@3303,1847.44 3326.34,1870.78 3344.47,1870.78 3356.59,1882.91 3356.59,1936.41 3325.41,1967.59 Q3_AMP12.1@3325.41,1984.57 ; Q2_AMP12.1@3303.41,1839.57 3303.41,1826.59 3353.6,1776.4 3353.6,1764.62 3367.22,1751 R4_AMP12.1@3367.22,1728 R4_AMP12.1@3368.6,1726.62 ; Q1_AMP12.3@3319.66,2229 3319.66,2162.66 3300.88,2143.88 3300.88,2016.56 Q3_AMP12.1@3325,1992.44 ; R4_AMP12.1@3368.6,1728 R4_AMP12.1@3368.6,1726.62 ; R4_AMP12.1@3370.49,1724.73 R4_AMP12.1@3368.6,1726.62 ; R2_AMP12.2@3383.4,1690 3383.4,1702.44 3368.6,1717.24 R4_AMP12.1@3368.6,1726.62
NetQ1_AMP13_3: Q1_AMP13.3 Q2_AMP13.1 Q3_AMP13.1 R2_AMP13.2 R4_AMP13.1 | length 623.9
  Top Layer w7: Q2_AMP13.1@3485,1847.44 3508.34,1870.78 3526.47,1870.78 3538.59,1882.91 3538.59,1936.41 3507.41,1967.59 Q3_AMP13.1@3507.41,1984.57 ; Q2_AMP13.1@3485.41,1839.57 3485.41,1826.59 3535.6,1776.4 3535.6,1764.62 3549.22,1751 R4_AMP13.1@3549.22,1728 R4_AMP13.1@3550.6,1726.62 ; Q1_AMP13.3@3501.66,2229 3501.66,2162.66 3482.88,2143.88 3482.88,2016.56 Q3_AMP13.1@3507,1992.44 ; R4_AMP13.1@3550.6,1728 R4_AMP13.1@3550.6,1726.62 ; R4_AMP13.1@3552.49,1724.73 R4_AMP13.1@3550.6,1726.62 ; R2_AMP13.2@3565.4,1690 3565.4,1702.44 3550.6,1717.24 R4_AMP13.1@3550.6,1726.62
NetQ1_AMP14_3: Q1_AMP14.3 Q2_AMP14.1 Q3_AMP14.1 R2_AMP14.2 R4_AMP14.1 | length 623.9
  Top Layer w7: Q2_AMP14.1@3667,1847.44 3690.34,1870.78 3708.47,1870.78 3720.59,1882.91 3720.59,1936.41 3689.41,1967.59 Q3_AMP14.1@3689.41,1984.57 ; Q2_AMP14.1@3667.41,1839.57 3667.41,1826.59 3717.6,1776.4 3717.6,1764.62 3731.22,1751 R4_AMP14.1@3731.22,1728 R4_AMP14.1@3732.6,1726.62 ; Q1_AMP14.3@3683.66,2229 3683.66,2162.66 3664.88,2143.88 3664.88,2016.56 Q3_AMP14.1@3689,1992.44 ; R4_AMP14.1@3732.6,1728 R4_AMP14.1@3732.6,1726.62 ; R4_AMP14.1@3734.49,1724.73 R4_AMP14.1@3732.6,1726.62 ; R2_AMP14.2@3747.4,1690 3747.4,1702.44 3732.6,1717.24 R4_AMP14.1@3732.6,1726.62
NetQ1_AMP15_3: Q1_AMP15.3 Q2_AMP15.1 Q3_AMP15.1 R2_AMP15.2 R4_AMP15.1 | length 623.9
  Top Layer w7: Q2_AMP15.1@3849,1847.44 3872.34,1870.78 3890.47,1870.78 3902.59,1882.91 3902.59,1936.41 3871.41,1967.59 Q3_AMP15.1@3871.41,1984.57 ; Q2_AMP15.1@3849.41,1839.57 3849.41,1826.59 3899.6,1776.4 3899.6,1764.62 3913.22,1751 R4_AMP15.1@3913.22,1728 R4_AMP15.1@3914.6,1726.62 ; Q1_AMP15.3@3865.66,2229 3865.66,2162.66 3846.88,2143.88 3846.88,2016.56 Q3_AMP15.1@3871,1992.44 ; R4_AMP15.1@3914.6,1728 R4_AMP15.1@3914.6,1726.62 ; R4_AMP15.1@3916.49,1724.73 R4_AMP15.1@3914.6,1726.62 ; R2_AMP15.2@3929.4,1690 3929.4,1702.44 3914.6,1717.24 R4_AMP15.1@3914.6,1726.62
NetQ1_AMP16_3: Q1_AMP16.3 Q2_AMP16.1 Q3_AMP16.1 R2_AMP16.2 R4_AMP16.1 | length 623.9
  Top Layer w7: Q2_AMP16.1@4033,1847.44 4056.34,1870.78 4074.47,1870.78 4086.59,1882.91 4086.59,1936.41 4055.41,1967.59 Q3_AMP16.1@4055.41,1984.57 ; Q2_AMP16.1@4033.41,1839.57 4033.41,1826.59 4083.6,1776.4 4083.6,1764.62 4097.22,1751 R4_AMP16.1@4097.22,1728 R4_AMP16.1@4098.6,1726.62 ; Q1_AMP16.3@4049.66,2229 4049.66,2162.66 4030.88,2143.88 4030.88,2016.56 Q3_AMP16.1@4055,1992.44 ; R4_AMP16.1@4098.6,1728 R4_AMP16.1@4098.6,1726.62 ; R4_AMP16.1@4100.49,1724.73 R4_AMP16.1@4098.6,1726.62 ; R2_AMP16.2@4113.4,1690 4113.4,1702.44 4098.6,1717.24 R4_AMP16.1@4098.6,1726.62
NetQ1_AMP17_3: Q1_AMP17.3 Q2_AMP17.1 Q3_AMP17.1 R2_AMP17.2 R4_AMP17.1 | length 623.9
  Top Layer w7: Q2_AMP17.1@4216,1847.44 4239.34,1870.78 4257.47,1870.78 4269.59,1882.91 4269.59,1936.41 4238.41,1967.59 Q3_AMP17.1@4238.41,1984.57 ; Q2_AMP17.1@4216.41,1839.57 4216.41,1826.59 4266.6,1776.4 4266.6,1764.62 4280.22,1751 R4_AMP17.1@4280.22,1728 R4_AMP17.1@4281.6,1726.62 ; Q1_AMP17.3@4232.66,2229 4232.66,2162.66 4213.88,2143.88 4213.88,2016.56 Q3_AMP17.1@4238,1992.44 ; R4_AMP17.1@4281.6,1728 R4_AMP17.1@4281.6,1726.62 ; R4_AMP17.1@4283.49,1724.73 R4_AMP17.1@4281.6,1726.62 ; R2_AMP17.2@4296.4,1690 4296.4,1702.44 4281.6,1717.24 R4_AMP17.1@4281.6,1726.62
NetQ1_AMP18_3: Q1_AMP18.3 Q2_AMP18.1 Q3_AMP18.1 R2_AMP18.2 R4_AMP18.1 | length 623.9
  Top Layer w7: Q2_AMP18.1@4398,1847.44 4421.34,1870.78 4439.47,1870.78 4451.59,1882.91 4451.59,1936.41 4420.41,1967.59 Q3_AMP18.1@4420.41,1984.57 ; Q2_AMP18.1@4398.41,1839.57 4398.41,1826.59 4448.6,1776.4 4448.6,1764.62 4462.22,1751 R4_AMP18.1@4462.22,1728 R4_AMP18.1@4463.6,1726.62 ; Q1_AMP18.3@4414.66,2229 4414.66,2162.66 4395.88,2143.88 4395.88,2016.56 Q3_AMP18.1@4420,1992.44 ; R4_AMP18.1@4463.6,1728 R4_AMP18.1@4463.6,1726.62 ; R4_AMP18.1@4465.49,1724.73 R4_AMP18.1@4463.6,1726.62 ; R2_AMP18.2@4478.4,1690 4478.4,1702.44 4463.6,1717.24 R4_AMP18.1@4463.6,1726.62
NetQ1_AMP19_3: Q1_AMP19.3 Q2_AMP19.1 Q3_AMP19.1 R2_AMP19.2 R4_AMP19.1 | length 623.9
  Top Layer w7: Q2_AMP19.1@4580,1847.44 4603.34,1870.78 4621.47,1870.78 4633.59,1882.91 4633.59,1936.41 4602.41,1967.59 Q3_AMP19.1@4602.41,1984.57 ; Q2_AMP19.1@4580.41,1839.57 4580.41,1826.59 4630.6,1776.4 4630.6,1764.62 4644.22,1751 R4_AMP19.1@4644.22,1728 R4_AMP19.1@4645.6,1726.62 ; Q1_AMP19.3@4596.66,2229 4596.66,2162.66 4577.88,2143.88 4577.88,2016.56 Q3_AMP19.1@4602,1992.44 ; R4_AMP19.1@4645.6,1728 R4_AMP19.1@4645.6,1726.62 ; R4_AMP19.1@4647.49,1724.73 R4_AMP19.1@4645.6,1726.62 ; R2_AMP19.2@4660.4,1690 4660.4,1702.44 4645.6,1717.24 R4_AMP19.1@4645.6,1726.62
NetQ1_AMP20_3: Q1_AMP20.3 Q2_AMP20.1 Q3_AMP20.1 R2_AMP20.2 R4_AMP20.1 | length 623.9
  Top Layer w7: Q2_AMP20.1@4763,1847.44 4786.34,1870.78 4804.47,1870.78 4816.59,1882.91 4816.59,1936.41 4785.41,1967.59 Q3_AMP20.1@4785.41,1984.57 ; Q2_AMP20.1@4763.41,1839.57 4763.41,1826.59 4813.6,1776.4 4813.6,1764.62 4827.22,1751 R4_AMP20.1@4827.22,1728 R4_AMP20.1@4828.6,1726.62 ; Q1_AMP20.3@4779.66,2229 4779.66,2162.66 4760.88,2143.88 4760.88,2016.56 Q3_AMP20.1@4785,1992.44 ; R4_AMP20.1@4828.6,1728 R4_AMP20.1@4828.6,1726.62 ; R4_AMP20.1@4830.49,1724.73 R4_AMP20.1@4828.6,1726.62 ; R2_AMP20.2@4843.4,1690 4843.4,1702.44 4828.6,1717.24 R4_AMP20.1@4828.6,1726.62
NetQ1_AMP21_3: Q1_AMP21.3 Q2_AMP21.1 Q3_AMP21.1 R2_AMP21.2 R4_AMP21.1 | length 623.9
  Top Layer w7: Q2_AMP21.1@4946,1847.54 4969.34,1870.89 4987.47,1870.89 4999.59,1883.01 4999.59,1936.51 4968.41,1967.69 Q3_AMP21.1@4968.41,1984.67 ; Q2_AMP21.1@4946.41,1839.67 4946.41,1826.69 4996.6,1776.5 4996.6,1764.72 5010.22,1751.1 R4_AMP21.1@5010.22,1728.1 R4_AMP21.1@5011.6,1726.72 ; Q1_AMP21.3@4962.66,2229.1 4962.66,2162.76 4943.88,2143.98 4943.88,2016.67 Q3_AMP21.1@4968,1992.54 ; R4_AMP21.1@5011.6,1728.1 R4_AMP21.1@5011.6,1726.72 ; R4_AMP21.1@5013.49,1724.83 R4_AMP21.1@5011.6,1726.72 ; R2_AMP21.2@5026.4,1690.1 5026.4,1702.54 5011.6,1717.35 R4_AMP21.1@5011.6,1726.72
NetQ1_AMP22_3: Q1_AMP22.3 Q2_AMP22.1 Q3_AMP22.1 R2_AMP22.2 R4_AMP22.1 | length 623.9
  Top Layer w7: Q2_AMP22.1@5128,1847.54 5151.34,1870.89 5169.47,1870.89 5181.59,1883.01 5181.59,1936.51 5150.41,1967.69 Q3_AMP22.1@5150.41,1984.67 ; Q2_AMP22.1@5128.41,1839.67 5128.41,1826.69 5178.6,1776.5 5178.6,1764.72 5192.22,1751.1 R4_AMP22.1@5192.22,1728.1 R4_AMP22.1@5193.6,1726.72 ; Q1_AMP22.3@5144.66,2229.1 5144.66,2162.76 5125.88,2143.98 5125.88,2016.67 Q3_AMP22.1@5150,1992.54 ; R4_AMP22.1@5193.6,1728.1 R4_AMP22.1@5193.6,1726.72 ; R4_AMP22.1@5195.49,1724.83 R4_AMP22.1@5193.6,1726.72 ; R2_AMP22.2@5208.4,1690.1 5208.4,1702.54 5193.6,1717.35 R4_AMP22.1@5193.6,1726.72
NetQ1_AMP23_3: Q1_AMP23.3 Q2_AMP23.1 Q3_AMP23.1 R2_AMP23.2 R4_AMP23.1 | length 623.9
  Top Layer w7: Q2_AMP23.1@5310,1847.54 5333.34,1870.89 5351.47,1870.89 5363.59,1883.01 5363.59,1936.51 5332.41,1967.69 Q3_AMP23.1@5332.41,1984.67 ; Q2_AMP23.1@5310.41,1839.67 5310.41,1826.69 5360.6,1776.5 5360.6,1764.72 5374.22,1751.1 R4_AMP23.1@5374.22,1728.1 R4_AMP23.1@5375.6,1726.72 ; Q1_AMP23.3@5326.66,2229.1 5326.66,2162.76 5307.88,2143.98 5307.88,2016.67 Q3_AMP23.1@5332,1992.54 ; R4_AMP23.1@5375.6,1728.1 R4_AMP23.1@5375.6,1726.72 ; R4_AMP23.1@5377.49,1724.83 R4_AMP23.1@5375.6,1726.72 ; R2_AMP23.2@5390.4,1690.1 5390.4,1702.54 5375.6,1717.35 R4_AMP23.1@5375.6,1726.72
NetQ1_AMP24_3: Q1_AMP24.3 Q2_AMP24.1 Q3_AMP24.1 R2_AMP24.2 R4_AMP24.1 | length 623.9
  Top Layer w7: Q2_AMP24.1@5492,1847.54 5515.34,1870.89 5533.47,1870.89 5545.59,1883.01 5545.59,1936.51 5514.41,1967.69 Q3_AMP24.1@5514.41,1984.67 ; Q2_AMP24.1@5492.41,1839.67 5492.41,1826.69 5542.6,1776.5 5542.6,1764.72 5556.22,1751.1 R4_AMP24.1@5556.22,1728.1 R4_AMP24.1@5557.6,1726.72 ; Q1_AMP24.3@5508.66,2229.1 5508.66,2162.76 5489.88,2143.98 5489.88,2016.67 Q3_AMP24.1@5514,1992.54 ; R4_AMP24.1@5557.6,1728.1 R4_AMP24.1@5557.6,1726.72 ; R4_AMP24.1@5559.49,1724.83 R4_AMP24.1@5557.6,1726.72 ; R2_AMP24.2@5572.4,1690.1 5572.4,1702.54 5557.6,1717.35 R4_AMP24.1@5557.6,1726.72
NetQ1_AMP25_3: Q1_AMP25.3 Q2_AMP25.1 Q3_AMP25.1 R2_AMP25.2 R4_AMP25.1 | length 623.9
  Top Layer w7: Q2_AMP25.1@5674,1847.54 5697.34,1870.89 5715.47,1870.89 5727.59,1883.01 5727.59,1936.51 5696.41,1967.69 Q3_AMP25.1@5696.41,1984.67 ; Q2_AMP25.1@5674.41,1839.67 5674.41,1826.69 5724.6,1776.5 5724.6,1764.72 5738.22,1751.1 R4_AMP25.1@5738.22,1728.1 R4_AMP25.1@5739.6,1726.72 ; Q1_AMP25.3@5690.66,2229.1 5690.66,2162.76 5671.88,2143.98 5671.88,2016.67 Q3_AMP25.1@5696,1992.54 ; R4_AMP25.1@5739.6,1728.1 R4_AMP25.1@5739.6,1726.72 ; R4_AMP25.1@5741.49,1724.83 R4_AMP25.1@5739.6,1726.72 ; R2_AMP25.2@5754.4,1690.1 5754.4,1702.54 5739.6,1717.35 R4_AMP25.1@5739.6,1726.72
NetQ1_AMP26_3: Q1_AMP26.3 Q2_AMP26.1 Q3_AMP26.1 R2_AMP26.2 R4_AMP26.1 | length 623.9
  Top Layer w7: Q2_AMP26.1@5857,1848.01 5880.34,1871.35 5898.47,1871.35 5910.59,1883.48 5910.59,1936.98 5879.41,1968.16 Q3_AMP26.1@5879.41,1985.14 ; Q2_AMP26.1@5857.41,1840.14 5857.41,1827.16 5907.6,1776.97 5907.6,1765.19 5921.22,1751.57 R4_AMP26.1@5921.22,1728.57 R4_AMP26.1@5922.6,1727.19 ; Q1_AMP26.3@5873.66,2229.57 5873.66,2163.23 5854.88,2144.45 5854.88,2017.13 Q3_AMP26.1@5879,1993.01 ; R4_AMP26.1@5922.6,1728.57 R4_AMP26.1@5922.6,1727.19 ; R4_AMP26.1@5924.49,1725.3 R4_AMP26.1@5922.6,1727.19 ; R2_AMP26.2@5937.4,1690.57 5937.4,1703.01 5922.6,1717.81 R4_AMP26.1@5922.6,1727.19
NetQ1_AMP27_3: Q1_AMP27.3 Q2_AMP27.1 Q3_AMP27.1 R2_AMP27.2 R4_AMP27.1 | length 623.9
  Top Layer w7: Q2_AMP27.1@6039,1848.01 6062.34,1871.35 6080.47,1871.35 6092.59,1883.48 6092.59,1936.98 6061.41,1968.16 Q3_AMP27.1@6061.41,1985.14 ; Q2_AMP27.1@6039.41,1840.14 6039.41,1827.16 6089.6,1776.97 6089.6,1765.19 6103.22,1751.57 R4_AMP27.1@6103.22,1728.57 R4_AMP27.1@6104.6,1727.19 ; Q1_AMP27.3@6055.66,2229.57 6055.66,2163.23 6036.88,2144.45 6036.88,2017.13 Q3_AMP27.1@6061,1993.01 ; R4_AMP27.1@6104.6,1728.57 R4_AMP27.1@6104.6,1727.19 ; R4_AMP27.1@6106.49,1725.3 R4_AMP27.1@6104.6,1727.19 ; R2_AMP27.2@6119.4,1690.57 6119.4,1703.01 6104.6,1717.81 R4_AMP27.1@6104.6,1727.19
NetQ1_AMP28_3: Q1_AMP28.3 Q2_AMP28.1 Q3_AMP28.1 R2_AMP28.2 R4_AMP28.1 | length 623.9
  Top Layer w7: Q2_AMP28.1@6221,1848.01 6244.34,1871.35 6262.47,1871.35 6274.59,1883.48 6274.59,1936.98 6243.41,1968.16 Q3_AMP28.1@6243.41,1985.14 ; Q2_AMP28.1@6221.41,1840.14 6221.41,1827.16 6271.6,1776.97 6271.6,1765.19 6285.22,1751.57 R4_AMP28.1@6285.22,1728.57 R4_AMP28.1@6286.6,1727.19 ; Q1_AMP28.3@6237.66,2229.57 6237.66,2163.23 6218.88,2144.45 6218.88,2017.13 Q3_AMP28.1@6243,1993.01 ; R4_AMP28.1@6286.6,1728.57 R4_AMP28.1@6286.6,1727.19 ; R4_AMP28.1@6288.49,1725.3 R4_AMP28.1@6286.6,1727.19 ; R2_AMP28.2@6301.4,1690.57 6301.4,1703.01 6286.6,1717.81 R4_AMP28.1@6286.6,1727.19
NetQ1_AMP29_3: Q1_AMP29.3 Q2_AMP29.1 Q3_AMP29.1 R2_AMP29.2 R4_AMP29.1 | length 623.9
  Top Layer w7: Q2_AMP29.1@6403,1848.01 6426.34,1871.35 6444.47,1871.35 6456.59,1883.48 6456.59,1936.98 6425.41,1968.16 Q3_AMP29.1@6425.41,1985.14 ; Q2_AMP29.1@6403.41,1840.14 6403.41,1827.16 6453.6,1776.97 6453.6,1765.19 6467.22,1751.57 R4_AMP29.1@6467.22,1728.57 R4_AMP29.1@6468.6,1727.19 ; Q1_AMP29.3@6419.66,2229.57 6419.66,2163.23 6400.88,2144.45 6400.88,2017.13 Q3_AMP29.1@6425,1993.01 ; R4_AMP29.1@6468.6,1728.57 R4_AMP29.1@6468.6,1727.19 ; R4_AMP29.1@6470.49,1725.3 R4_AMP29.1@6468.6,1727.19 ; R2_AMP29.2@6483.4,1690.57 6483.4,1703.01 6468.6,1717.81 R4_AMP29.1@6468.6,1727.19
NetQ1_AMP30_3: Q1_AMP30.3 Q2_AMP30.1 Q3_AMP30.1 R2_AMP30.2 R4_AMP30.1 | length 623.9
  Top Layer w7: Q2_AMP30.1@6585,1848.44 6608.34,1871.78 6626.47,1871.78 6638.59,1883.91 6638.59,1937.41 6607.41,1968.59 Q3_AMP30.1@6607.41,1985.57 ; Q2_AMP30.1@6585.41,1840.57 6585.41,1827.59 6635.6,1777.4 6635.6,1765.62 6649.22,1752 R4_AMP30.1@6649.22,1729 R4_AMP30.1@6650.6,1727.62 ; Q1_AMP30.3@6601.66,2230 6601.66,2163.66 6582.88,2144.88 6582.88,2017.56 Q3_AMP30.1@6607,1993.44 ; R4_AMP30.1@6650.6,1729 R4_AMP30.1@6650.6,1727.62 ; R4_AMP30.1@6652.49,1725.73 R4_AMP30.1@6650.6,1727.62 ; R2_AMP30.2@6665.4,1691 6665.4,1703.44 6650.6,1718.24 R4_AMP30.1@6650.6,1727.62
NetQ5_SUMMER1_1: Q5_SUMMER1.1 Q8_SUMMER1.2 R17_SUMMER1.2 | length 295.5
  Top Layer w7: Q5_SUMMER1.1@1728.34,2629.6 1728.34,2618.56 1739.9,2607 1899.74,2607 Q8_SUMMER1.2@1939.34,2567.4 ; Q5_SUMMER1.1@1730.94,2627 R17_SUMMER1.2@1783.22,2627
NetQ5_SUMMER1_2: Q5_SUMMER1.2 R14_SUMMER1.2 | length 52.5
  Top Layer w7: Q5_SUMMER1.2@1730.74,2702 R14_SUMMER1.2@1783.22,2702
NetQ5_SUMMER2_1: Q5_SUMMER2.1 Q8_SUMMER2.2 R17_SUMMER2.2 | length 295.5
  Top Layer w7: Q5_SUMMER2.1@2643.34,2629.6 2643.34,2618.56 2654.9,2607 2814.74,2607 Q8_SUMMER2.2@2854.34,2567.4 ; Q5_SUMMER2.1@2645.94,2627 R17_SUMMER2.2@2698.22,2627
NetQ5_SUMMER2_2: Q5_SUMMER2.2 R14_SUMMER2.2 | length 52.5
  Top Layer w7: Q5_SUMMER2.2@2645.74,2702 R14_SUMMER2.2@2698.22,2702
NetQ5_SUMMER3_1: Q5_SUMMER3.1 Q8_SUMMER3.2 R17_SUMMER3.2 | length 295.5
  Top Layer w7: Q5_SUMMER3.1@3551.34,2629.6 3551.34,2618.56 3562.9,2607 3722.74,2607 Q8_SUMMER3.2@3762.34,2567.4 ; Q5_SUMMER3.1@3553.94,2627 R17_SUMMER3.2@3606.22,2627
NetQ5_SUMMER3_2: Q5_SUMMER3.2 R14_SUMMER3.2 | length 52.5
  Top Layer w7: Q5_SUMMER3.2@3553.74,2702 R14_SUMMER3.2@3606.22,2702
NetQ5_SUMMER4_1: Q5_SUMMER4.1 Q8_SUMMER4.2 R17_SUMMER4.2 | length 295.5
  Top Layer w7: Q5_SUMMER4.1@4462.34,2629.6 4462.34,2618.56 4473.9,2607 4633.74,2607 Q8_SUMMER4.2@4673.34,2567.4 ; Q5_SUMMER4.1@4464.94,2627 R17_SUMMER4.2@4517.22,2627
NetQ5_SUMMER4_2: Q5_SUMMER4.2 R14_SUMMER4.2 | length 52.5
  Top Layer w7: Q5_SUMMER4.2@4464.74,2702 R14_SUMMER4.2@4517.22,2702
NetQ5_SUMMER5_1: Q5_SUMMER5.1 Q8_SUMMER5.2 R17_SUMMER5.2 | length 295.5
  Top Layer w7: Q5_SUMMER5.1@5375.34,2629.7 5375.34,2618.66 5386.9,2607.1 5546.74,2607.1 Q8_SUMMER5.2@5586.34,2567.5 ; Q5_SUMMER5.1@5377.94,2627.1 R17_SUMMER5.2@5430.22,2627.1
NetQ5_SUMMER5_2: Q5_SUMMER5.2 R14_SUMMER5.2 | length 52.5
  Top Layer w7: Q5_SUMMER5.2@5377.74,2702.1 R14_SUMMER5.2@5430.22,2702.1
NetQ5_SUMMER6_1: Q5_SUMMER6.1 Q8_SUMMER6.2 R17_SUMMER6.2 | length 295.5
  Top Layer w7: Q5_SUMMER6.1@6286.34,2630.17 6286.34,2619.13 6297.9,2607.57 6457.74,2607.57 Q8_SUMMER6.2@6497.34,2567.97 ; Q5_SUMMER6.1@6288.94,2627.57 R17_SUMMER6.2@6341.22,2627.57
NetQ5_SUMMER6_2: Q5_SUMMER6.2 R14_SUMMER6.2 | length 52.5
  Top Layer w7: Q5_SUMMER6.2@6288.74,2702.57 R14_SUMMER6.2@6341.22,2702.57
NetQ6_SUMMER1_2: Q6_SUMMER1.2 Q7_SUMMER1.1 R15_SUMMER1.1 | length 183.4
  Top Layer w7: Q7_SUMMER1.1@1438.59,2610.43 1438.59,2620.97 1404.56,2655 R15_SUMMER1.1@1391.78,2655 1391.78,2692.78 1424.43,2725.43 Q6_SUMMER1.2@1452.41,2725.43
NetQ6_SUMMER2_2: Q6_SUMMER2.2 Q7_SUMMER2.1 R15_SUMMER2.1 | length 183.4
  Top Layer w7: Q7_SUMMER2.1@2353.59,2610.43 2353.59,2620.97 2319.56,2655 R15_SUMMER2.1@2306.78,2655 2306.78,2692.78 2339.43,2725.43 Q6_SUMMER2.2@2367.41,2725.43
NetQ6_SUMMER3_2: Q6_SUMMER3.2 Q7_SUMMER3.1 R15_SUMMER3.1 | length 183.4
  Top Layer w7: Q7_SUMMER3.1@3261.59,2610.43 3261.59,2620.97 3227.56,2655 R15_SUMMER3.1@3214.78,2655 3214.78,2692.78 3247.43,2725.43 Q6_SUMMER3.2@3275.41,2725.43
NetQ6_SUMMER4_2: Q6_SUMMER4.2 Q7_SUMMER4.1 R15_SUMMER4.1 | length 183.4
  Top Layer w7: Q7_SUMMER4.1@4172.59,2610.43 4172.59,2620.97 4138.56,2655 R15_SUMMER4.1@4125.78,2655 4125.78,2692.78 4158.43,2725.43 Q6_SUMMER4.2@4186.41,2725.43
NetQ6_SUMMER5_2: Q6_SUMMER5.2 Q7_SUMMER5.1 R15_SUMMER5.1 | length 183.4
  Top Layer w7: Q7_SUMMER5.1@5085.59,2610.54 5085.59,2621.07 5051.56,2655.1 R15_SUMMER5.1@5038.78,2655.1 5038.78,2692.88 5071.43,2725.54 Q6_SUMMER5.2@5099.41,2725.54
NetQ6_SUMMER6_2: Q6_SUMMER6.2 Q7_SUMMER6.1 R15_SUMMER6.1 | length 183.4
  Top Layer w7: Q7_SUMMER6.1@5996.59,2611 5996.59,2621.54 5962.56,2655.57 R15_SUMMER6.1@5949.78,2655.57 5949.78,2693.35 5982.43,2726 Q6_SUMMER6.2@6010.41,2726
NetR21_2: R21.2 R22.1 VR1.1 | length 529.7
  Top Layer w7: R21.2@1426.85,3500 1426.85,3413.15 1433,3407 1537,3407 1599,3345 1606,3345 R22.1@1606,3230 ; 1606,3329 VR1.1@1726.44,3329
NetR23_2: R23.2 R24.1 VR2.1 | length 458.9
  Top Layer w7: R23.2@1300,3306.85 1300,3191 1343.37,3147.63 1343.37,3142.63 VR2.1@1381.6,3142.63 1381.6,3085.4 1388,3079 1498,3079 1514,3095 R24.1@1514,3133.22 R24.1@1514,3134.6
SIPMOUT1_SUMMER1: C5_AMP1.2 P1.C1 | length 2420.8
  Top Layer w7: C5_AMP1.2@1382.78,1817 1382,1817.78 1382,1910 v1(1398,1926) ; v1(1448,2856) 1448,2919 1595,3066 1677,3066 1743,3132 2450,3132 2475,3157 P1.C1@2475,3212.36
  Bottom Layer w7: v1(1398,1926) 1398,1949.32 1347,2000.32 1347,2024 1436,2113 1436,2169 1354,2251 1354,2350 1381,2377 1381,2789 v1(1448,2856)
SIPMOUT1_SUMMER2: C5_AMP6.2 P1.C6 | length 1911.5
  Top Layer w7: C5_AMP6.2@2297.78,1817 2297,1817.78 2297,1910 v1(2313,1926) ; v1(2628,2883) 2628,2918 2755,3045 2847,3045 2975,3173 P1.C6@2975,3212.36
  Bottom Layer w7: v1(2313,1926) 2313,1949.32 2262,2000.32 2262,2024 2351,2113 2351,2169 2269,2251 2269,2357 2289,2377 2289,2665 2507,2883 v1(2628,2883)
SIPMOUT1_SUMMER3: C5_AMP11.2 P1.C11 | length 1617.7
  Top Layer w7: C5_AMP11.2@3205.78,1817 3205,1817.78 3205,1910 v1(3221,1926) ; v1(3335,2873) 3335,2913 3475,3053 P1.C11@3475,3212.36
  Bottom Layer w7: v1(3221,1926) 3221,1949.32 3170,2000.32 3170,2024 3259,2113 3259,2169 3177,2251 3177,2385 3198,2406 3198,2736 v1(3335,2873)
SIPMOUT1_SUMMER4: C5_AMP16.2 P1.C16 | length 1556.8
  Top Layer w7: P1.C16@3975,3212.36 3975,3162 4060,3077 v1@4060,2868 ; C5_AMP16.2@4116.78,1817 4116,1817.78 4116,1910 v1(4132,1926)
  Bottom Layer w7: v1@4060,2868 v1(4060,2866) 4060,2813 4107,2766 4107,2406.55 4088,2387.55 4088,2251 4170,2169 4170,2113 4081,2024 4081,2000.32 4132,1949.32 v1(4132,1926)
SIPMOUT1_SUMMER5: C5_AMP21.2 P1.C21 | length 1787.6
  Top Layer w7: P1.C21@4475,3212.36 4475,3132 4729,2878 v1(4788,2878) ; C5_AMP21.2@5029.78,1817.1 5029,1817.88 5029,1910.1 v1(5045,1926.1)
  Bottom Layer w7: v1(4788,2878) 4841,2878 5013,2706 5013,2396 5001,2384 5001,2251.1 5083,2169.1 5083,2113.1 4994,2024.1 4994,2000.42 5045,1949.42 v1(5045,1926.1)
SIPMOUT1_SUMMER6: C5_AMP26.2 P1.C26 | length 2006.1
  Top Layer w7: P1.C26@4975,3212.36 5042.36,3145 5100,3145 5328,2917 v1(5422,2917) ; C5_AMP26.2@5940.78,1817.57 5940,1818.35 5940,1910.57 v1(5956,1926.57)
  Bottom Layer w7: v1(5422,2917) 5448,2917 5799,2566 5799,2562 5935,2426 5935,2401 5914,2380 5912,2380 5912,2251.57 5994,2169.57 5994,2113.57 5905,2024.57 5905,2000.89 5956,1949.89 v1(5956,1926.57)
